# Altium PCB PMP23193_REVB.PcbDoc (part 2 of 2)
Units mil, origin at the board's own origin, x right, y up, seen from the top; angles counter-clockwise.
Board outline 5000 x 3500 mil, 4 copper layers (Component Side, Signal Layer 1, Signal Layer 2, Solder Side), stack 33.234 mil thick; 89 components, 40 nets, 217 pads, 130 vias.
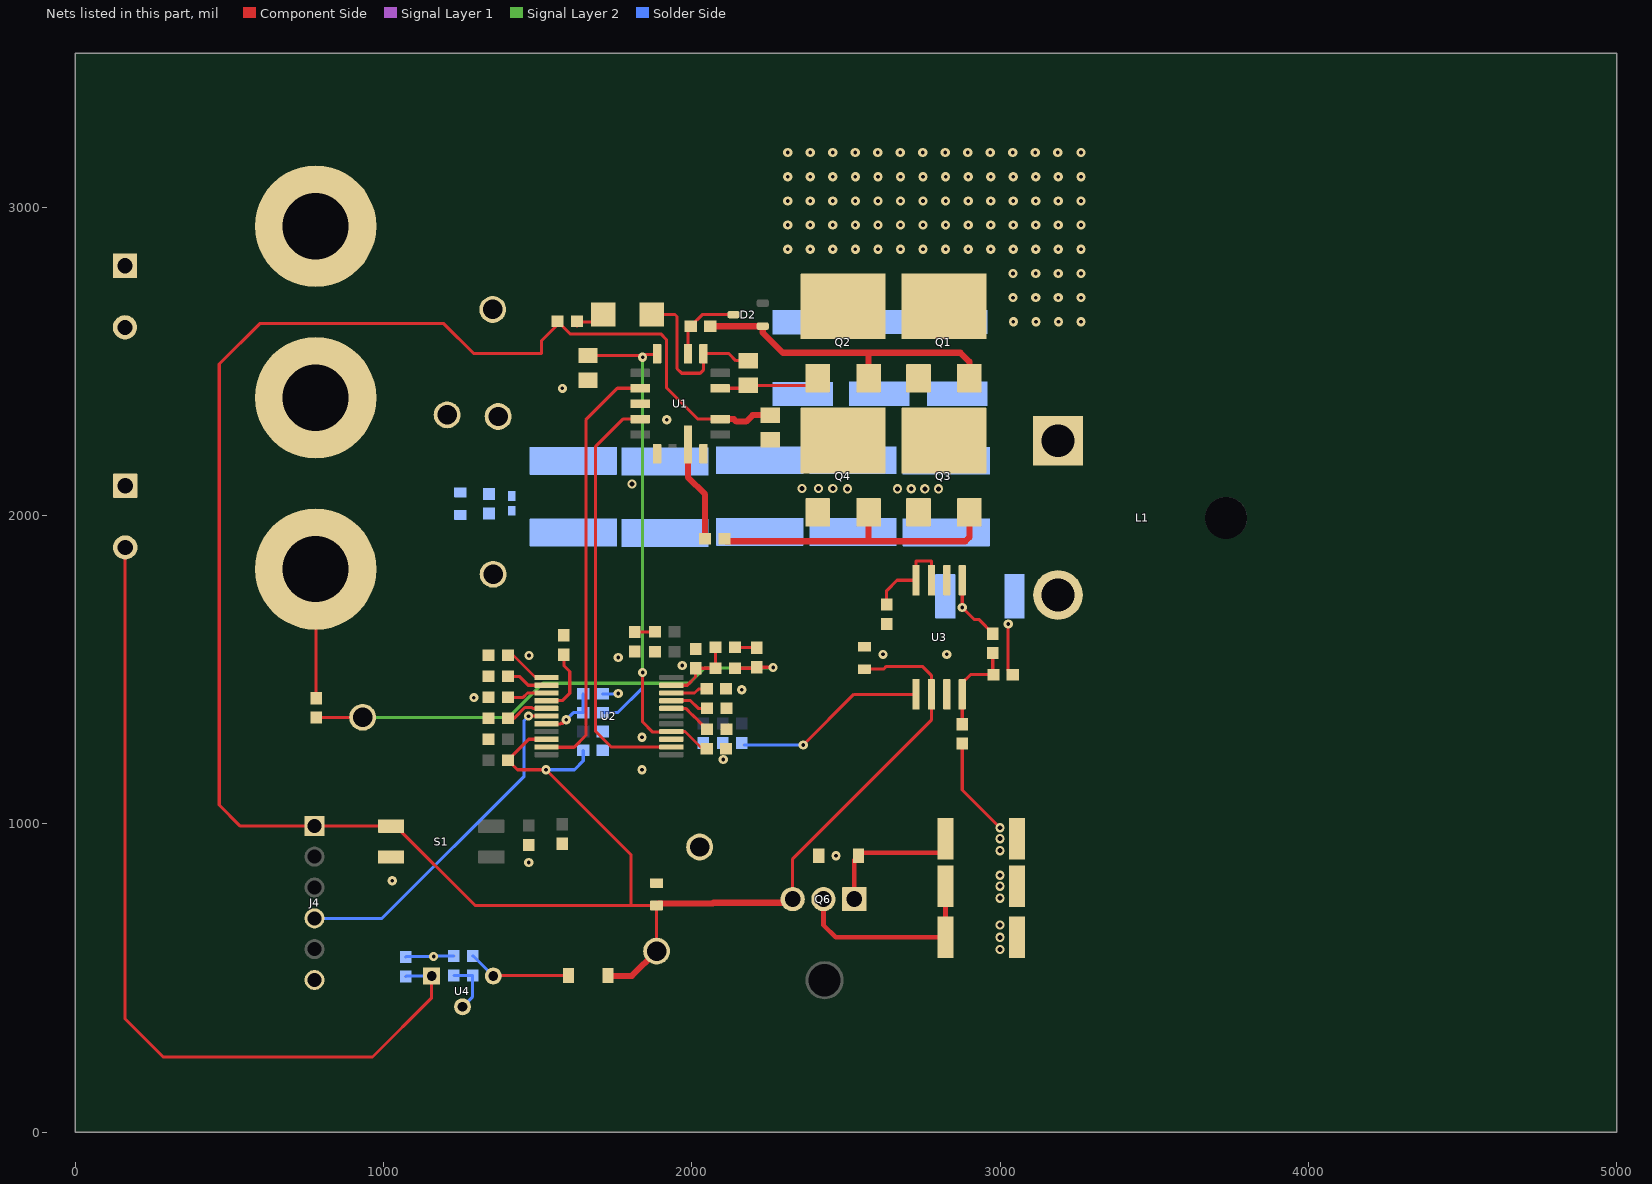
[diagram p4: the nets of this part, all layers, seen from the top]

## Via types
v1: diameter 30, hole 12, Component Side to Solder Side, tented both sides, 112 vias
v2: diameter 30, hole 16, Component Side to Solder Side, tented both sides, 18 vias

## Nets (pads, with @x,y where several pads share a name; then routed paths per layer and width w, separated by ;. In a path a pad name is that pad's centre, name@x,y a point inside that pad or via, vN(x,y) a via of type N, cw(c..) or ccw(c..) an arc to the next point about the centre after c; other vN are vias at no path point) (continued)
GND: C1.1 C2.2 C3.2 C11.2 C13.2 C15.1 C16.2 C17.2 C18.1 C19.1 C20.1 C21.1 C22.1 C23.2 C24.2 C26.2 C27.2 C28.2 C29.2 C30.1 C33.2 C35.1 C37.2 C38.2 C39.2 C200.2 D4.2 J1.2 J3.1 J4.6 J7.1 Q3.3 Q4.3 R6.1 R15.1 R16.1 R17.1 R18.1 R20.1 R21.1 R24.1 R25.1 R29.1 R31.1 R33.1 S1.4 TP2.1 TP4.1 TP7.1 U1.2 U1.14 U1.17 U2.14 U3.2 U3.7 | length 207.9
  Solder Side w10: C38.2@1072,568.5 1074,570.5 v1(1162.31,570.5) 1163.31,571.5 R33.1@1228,571.5 ; R24.1@1710.77,1422 1760,1422 v1(1761,1423)
  other v1: 1028,816 1471,875 2467.32,897 1838.57,1176 2101.89,1209 1838.57,1281.33 1293,1410 2162,1435.5 1968.93,1513.91 1761,1540 1471.93,1546.48 2619.91,1550.17 2827,1550.17 1918.5,2311.04 1580,2413
  other v2: 2504.97,2087.15 2667.1,2087.1 2755.6,2087.1 2799.96,2087.1 2357.63,2088.23 2410.81,2088.23 2457.31,2088.23 2711.71,2087.52 1805.5,2103.2
HIN: U1.13 U2.10 | length 1386.3
  Component Side w10: U2.10@1528.44,1249.04 1618.2,1249.04 1656,1286.84 1656,2311.04 1758.3,2413.34 U1.13@1832.56,2413.34
HOVgs: D2.1 Q1.2 Q2.2 R3.2 | length 1036.3
  Component Side w20: R3.2@2059.46,2615.29 2059.99,2614.75 D2.1@2230,2614.75 2230,2594.04 2295.51,2528.53 2573.18,2528.53 2573.33,2528.67 ; Q2.2@2573.33,2446.28 2573.33,2528.53 2871.1,2528.53 2900.1,2499.53 Q1.2@2900.1,2446.28
LIN: U1.15 U2.13 | length 1372.4
  Component Side w10: U1.15@1832.56,2313.34 1776.3,2313.34 1688,2225.04 1688,1300.03 1738.01,1250.02 U2.13@1933.56,1250.02
LOVgs: Q3.2 Q4.2 R4.2 | length 977.6
  Component Side w20: R4.2@2105.72,1924.67 2113.4,1916.98 2571.65,1916.98 2573.33,1918.66 ; Q4.2@2573.33,2010.88 2573.33,1918.66 ; Q3.2@2900.1,2010.88 2900.1,1929.69 2887.39,1916.98 2575,1916.98 2573.33,1918.66
NetC10_1: C10.1 D1.1 U1.8 | length 557.8
  Component Side w10: D1.1@1869.76,2652.71 1945.42,2652.71 1952,2646.12 1952,2477.04 1967,2462.04 2027,2462.04 2037.28,2472.32 U1.8@2037.28,2525.54 2120.24,2525.54 2142.76,2503.02 C10.1@2182.76,2503.02
NetC23_1: C23.1 U2.18 | length 145.2
  Component Side w10: U2.18@1933.56,1375.02 1980.03,1375.02 2002.18,1352.87 2003.36,1352.87 2019.68,1336.55 2019.68,1335.36 2020.67,1335.36 C23.1@2048.91,1307.12 C23.1@2047.93,1307.12
NetC24_1: C24.1 U2.5 | length 141
  Component Side w10: C24.1@1403.05,1343.04 1423.62,1343.04 1458.45,1377.87 1481.55,1377.87 1484.4,1375.02 U2.5@1528.44,1375.02
NetC25_2: C25.2 R29.2 | length 66.2
  Component Side w10: R29.2@1815,1622.53 1880.5,1622.53 C25.2@1881,1623.04
NetC28_1: C28.1 U2.20 | length 120.2
  Component Side w10: U2.20@1933.56,1425.02 2008.72,1425.02 2021.85,1438.15 C28.1@2048.27,1438.15
NetC34_1: C34.1 R23.1 | length 70.9
  Component Side w10: C34.1@2139.72,1573.03 2208.45,1573.03 R23.1@2209.99,1571.5
NetC37_1: C37.1 U3.3 U3.4 | length 329
  Component Side w10: C37.1@2632,1711.53 2632,1757.04 2665.69,1790.73 U3.4@2727,1790.73 2727,1853 2777,1853 U3.3@2777,1790.73
NetC201_1: C201.1 R200.2 R201.1 U3.8 | length 316.7
  Component Side w10: R201.1@2877,1323.55 U3.8@2877,1420.65 2877,1458.05 2903.6,1484.66 R200.2@2977.89,1484.66 2976.09,1486.46 C201.1@2976.09,1554.19
NetD1_2: D1.2 R1.2 | length 97.9
  Component Side w10: R1.2@1636.65,2629.04 D1.2@1688.61,2629.04
  Component Side w20: R1.2@1627.83,2620.23 R1.2@1636.65,2629.04 ; D1.2@1688.61,2629.04 D1.2@1712.28,2652.71
NetD2_3: D2.3 R3.1 U1.9 | length 247.9
  Component Side w10: U1.9@1987.28,2525.54 1987.28,2606.11 R3.1@1996.46,2615.29 2033.33,2652.15 D2.3@2135.51,2652.15
NetD4_1: D4.1 Q6.1 R10.1 | length 479.1
  Component Side w15: Q6.1@2526.93,744.57 2526.93,883.19 D4.1@2540.57,896.83 2550.41,906.68 2804.51,906.68 2822.6,924.77 R10.1@2822.6,952.36
NetD6_2: D6.2 R13.2 U4.3 | length 338.1
  Component Side w10: U4.3@1356,507.04 1357.96,509 D6.2@1599.53,509
  Solder Side w10: R13.2@1288.96,571.5 1291.54,571.5 U4.3@1356,507.04
NetL1_2: L1.2 R32.1 R200.1 | length 170.6
  Component Side w10: v1(3025.97,1648.54) 3025.97,1499.57 3026.2,1499.34 3026.2,1498.36 3039.9,1484.66 R200.1@3040.89,1484.66
NetQ6_2: Q6.2 R11.1 R12.1 | length 650.5
  Component Side w15: Q6.2@2426.93,744.57 2426.93,672.07 2466.54,632.46 R12.1@2822.6,632.46 R11.1@2822.6,798.41
NetR4_1: R4.1 U1.1 | length 329.4
  Component Side w20: U1.1@1987.28,2231.15 1987.28,2124.6 2042.72,2069.16 R4.1@2042.72,1924.67
NetR13_1: R13.1 R33.2 U4.2 | length 176.1
  Solder Side w10: R33.2@1228,508.5 R13.1@1288.96,508.5 1288.96,440 U4.2@1256,407.04
NetR14_2: R14.2 R23.2 R28.1 TP8.1 | length 1687.6
  Component Side w10: R28.1@781,1345.05 780.55,1345.5 TP8.1@931.87,1345.5 ; R14.2@2139.72,1505.22 2206.7,1505.22 R23.2@2209.99,1508.5 2262.63,1508.5 v1(2263.58,1507.55)
  Signal Layer 1 w10: TP8.1@932,1346 TP8.1@932,1367
  Signal Layer 2 w10: TP8.1@932,1346 1406,1346 1516.61,1456.61 1991.85,1456.61 2041.67,1506.44 v1@2254.61,1506.44
NetR15_2: R15.2 U2.3 | length 131.3
  Component Side w10: R15.2@1403.05,1410.88 1452.88,1410.88 1467.02,1425.02 U2.3@1528.44,1425.02
NetR16_2: R16.2 U2.2 | length 137.3
  Component Side w10: R16.2@1403.05,1478.78 1440.3,1478.78 1469.06,1450.02 U2.2@1528.44,1450.02
NetR17_2: R17.2 U2.1 | length 155.1
  Component Side w10: R17.2@1403.05,1546.69 1421.31,1546.69 1492.98,1475.02 U2.1@1528.44,1475.02
NetR19_1: R19.1 R24.2 U2.7 | length 203.4
  Component Side w10: U2.7@1528.44,1325.02 1573.6,1325.02 1575.45,1326.87 1581.37,1326.87 v1(1592.82,1338.32)
  Solder Side w10: v1@1587,1332.5 v1(1592.82,1338.32) 1615.54,1361.05 R19.1@1647.78,1361.05 R24.2@1647.78,1422
NetR20_2: R20.2 U2.4 | length 218.6
  Component Side w10: U2.4@1528.44,1400.02 1580.02,1400.02 1603.82,1423.82 1603.82,1494.73 1584.63,1513.91 R20.2@1584.63,1549.19
NetR25_2: R25.2 U2.19 | length 125.7
  Component Side w10: U2.19@1933.56,1400.02 1995.39,1400.02 2020.39,1375.02 R25.2@2048.91,1375.02
NetR30_2: R30.2 U3.5 | length 626.1
  Component Side w10: v1(2360.93,1256) 2525.58,1420.65 U3.5@2727,1420.65
  Solder Side w10: R30.2@2169.1,1256 v1(2360.93,1256)
SW: C10.2 L1.1 Q1.3 Q2.3 Q3.1 Q4.1 U1.6 | length 330
  Component Side w10: U1.6@2092.01,2413.34 C10.2@2173.07,2413.34 ; C10.2@2182.76,2423.02 2385.07,2423.02 Q2.3@2408.33,2446.28
  Component Side w20: C10.2@2173.07,2413.34 C10.2@2182.76,2423.02
SYNC: J4.4 U2.6 | length 1145.1
  Component Side w10: v1(1470,1350) U2.6@1528.44,1350.02
  Solder Side w10: J4.4@776,694 995,694 ; 1005.57,704.57 995,694 ; v1(1470,1350) 1456,1336 1456,1155 995,694
Vbias: C13.1 C30.2 C33.1 C35.2 D6.1 J4.1 Q6.3 R1.1 R8.2 S1.3 TP6.1 U1.4 U2.9 U3.6 | length 8117.7
  Component Side w10: U2.9@1528.44,1275.02 1470.9,1275.02 R8.2@1403.05,1207.16 1434.21,1176 v1(1527,1176) 1802,901 1802,735.42 ; R1.1@1564.57,2630.04 1604.61,2590 1899,2590 1918,2571 1918,2415 2019.66,2313.34 U1.4@2092.01,2313.34 ; R1.1@1564.84,2620.23 1512.83,2568.22 1512.83,2526.03 1292.3,2526.03 1195.33,2623 598,2623 467,2492 467,1061.42 535.38,993.04 S1.3@1024.6,993.04 1039.62,993.04 1297.25,735.42 1802,735.42 ; TP6.1@1885.59,587.78 C30.2@1885.59,735.42 1802,735.42 ; Q6.3@2326.93,744.57 2326.93,886.93 2777,1337 U3.6@2777,1420.65 2777,1482 2747.46,1511.54 2631,1511.54 2621.74,1502.28 C35.2@2560,1502.28
  Component Side w20: D6.1@1728.47,509 1730.43,507.04 1804.85,507.04 TP6.1@1885.59,587.78 ; C30.2@1885.59,735.42 1892.09,741.91 2067.68,741.91 2070.33,744.57 Q6.3@2326.93,744.57 ; U1.4@2092.01,2313.34 2136.21,2313.34 2144.28,2305.27 2175.87,2305.27 2196.81,2326.21 C13.1@2254.61,2326.21
  Solder Side w10: v1(1527,1176) 1619.06,1176 1647.78,1204.72 C33.1@1647.78,1239.01
Vfb: C34.2 R14.1 R21.2 U2.21 | length 250.5
  Component Side w10: U2.21@1933.56,1450.02 1985.26,1450.02 2011.93,1476.7 R21.2@2011.93,1505.22 R14.1@2076.72,1505.22 C34.2@2076.72,1573.03
Vin: C1.2 C2.1 C3.1 J1.1 J2.1 Q1.1 Q2.1 R10.2 R11.2 R12.2 R201.2 TP1.1 | length 323.4
  Component Side w10: R201.2@2877,1260.56 2877,1110.44 v2(2999.54,987.9)
  other v1: 3043,2629 3116,2629 3189,2629 3262,2629 3041.67,2707.43 3115.11,2707.43 3188.56,2707.43 3262,2707.43 3041.67,2785.86 3115.11,2785.86 3188.56,2785.86 3262,2785.86 2311,2864.29 2384.15,2864.29 2457.31,2864.29 2530.46,2864.29 2603.62,2864.29 2676.77,2864.29 2749.92,2864.29 2823.08,2864.29 2896.23,2864.29 2969.38,2864.29 3042.54,2864.29 3115.69,2864.29 3188.85,2864.29 3262,2864.29 2311,2942.71 2384.15,2942.71 2457.31,2942.71 2530.46,2942.71 2603.62,2942.71 2676.77,2942.71 2749.92,2942.71 2823.08,2942.71 2896.23,2942.71 2969.38,2942.71 3042.54,2942.71 3115.69,2942.71 3188.85,2942.71 3262,2942.71 2311,3021.14 2384.15,3021.14 2457.31,3021.14 2530.46,3021.14 2603.62,3021.14 2676.77,3021.14 2749.92,3021.14 2823.08,3021.14 2896.23,3021.14 2969.38,3021.14 3042.54,3021.14 3115.69,3021.14 3188.85,3021.14 3262,3021.14 2311,3099.57 2384.15,3099.57 2457.31,3099.57 2530.46,3099.57 2603.62,3099.57 2676.77,3099.57 2749.92,3099.57 2823.08,3099.57 2896.23,3099.57 2969.38,3099.57 3042.54,3099.57 3115.69,3099.57 3188.85,3099.57 3262,3099.57 2311,3178 2384,3178 2457,3178 2530,3178 2603,3178 2676,3178 2749,3178 2822,3178 2895,3178 2968,3178 3041,3178 3114,3178 3187,3178 3262,3178
  other v2: 2999.54,592.99 2999.29,632.46 2999.29,672.07 2999.29,759.4 2999.54,798.39 2999.54,833.69 2999.54,913.58 2999.54,952.36
VLDO: C11.1 C27.1 R19.2 U1.11 U2.15 | length 1877.8
  Component Side w10: C11.1@1663.17,2519.56 1838.39,2519.56 1841.7,2522.87 1883.64,2522.87 U1.11@1886.8,2526.03 ; v1(1840.25,1491.37) 1840.25,1330.75 1873,1298 1931.54,1298 U2.15@1933.56,1300.02 1977.96,1300.02 2034.46,1243.52 C27.1@2048.27,1243.52
  Component Side w20: U1.11@1886.8,2526.03 U1.11@1887.28,2525.54
  Signal Layer 1 w10: v1@1840.25,2521.42 v1@1841.7,2522.87
  Signal Layer 2 w10: v1(1840.25,1491.37) v1@1840.25,2521.42
  Solder Side w10: R19.2@1710.77,1361.05 1759.02,1361.05 1840.25,1442.27 v1(1840.25,1491.37)
  other v1: 1840.25,2513.89
Vout: C15.2 C16.1 C17.1 C18.2 C19.2 C20.2 C21.2 C22.2 C38.1 C201.2 J3.2 J6.1 R28.2 R32.2 TP3.1 U3.1 U4.1 | length 3440.4
  Component Side w10: J3.2@161.1,1884.2 161.1,367.9 285,244 964,244 1156,436 U4.1@1156,507.04 ; J6.1@779.7,1826.72 781,1825.42 R28.2@781,1408.04 ; U3.1@2877,1790.73 v1(2877,1702.04) 2915.35,1663.69 2930.57,1663.69 2976.09,1618.17 C201.2@2976.09,1617.19
  Solder Side w10: C38.1@1072,505.5 1073.53,507.04 U4.1@1156,507.04
pads on no net: D2.2 H1.1 J4.2 J4.3 J4.5 L1. U1.3 U1.7 U1.12 U1.16 U1.18 U2.11 U2.12

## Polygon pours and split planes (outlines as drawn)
GND on Solder Side "Solder Side-SGND" (solid, pour order 24): 0,0 5000,0 5000,3500 0,3500
Vout on Solder Side "Solder Side-Vout" (solid, pour order 6): 2985.09,2031 2985.09,1585.69 0,1585.69 0,2031
NetL1_2 on Solder Side "Solder Side-IN+" (solid, pour order 15): 3005,1586 3005,1900.94 3029.09,1925.04 3311,1925.04 3311,1586
Vin on Solder Side "Solder Side-Vin" (solid, pour order 2): 5000,2564.9 5000,3500 0,3500 0,2756 570.4,2756 623.7,2702.7 1038.3,2702.7 1176.1,2564.9
Vin on Component Side "Component Side-Vin" (solid, pour order 0): 3106,539.07 3106,1044 2958.42,1044 2958.43,539.07
GND on Component Side "Component Side-SGND" (solid, remove dead copper, pour order 25): 0,0 0,3500 5000,3500 5000,0
SW on Component Side "Component Side-SW" (solid, pour order 16): 2352,2350.21 2352,2493.04 2448.13,2493.04 2448.13,2400 2497.92,2350.21 2678,2350.21 2678,2493.04 2775,2493.04 2775,2400.13 2824.92,2350.21 3271.34,2350.21 3271.34,2137.58 2954.86,2137.58 2352,2138.52
Vin on Component Side "Component Side-Vin" (solid, pour order 10): 3305,2564.9 3305,3225 2270,3225 2270,2564.9
Vin on Signal Layer 2 "Signal Layer 2-GND" (solid, pour order 18): 0,0 5000,0 5000,3500 0,3500
GND on Signal Layer 1 "Signal Layer 2-GND" (solid, pour order 22): 0,0 5000,0 5000,3500 0,3500

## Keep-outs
Keep-Out Layer:
  text ".Layer_Name" at 577,-858.49 h60

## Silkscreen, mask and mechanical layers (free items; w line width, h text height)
Top Overlay:
  text "VIN" at 84,2996 h100
  text "VOUT" at 84,1586 h100
  text "Vbias" at 409,972 h60
  text "SYNC" at 457.63,658.16 h60
  text "SGND" at 447.91,465 h60
  text "'.PRJ_Number'.PCB_Rev" at 4113.85,124 h108.27
  text ".Layer_Name" at 577,-858.49 h60
Bottom Overlay:
  text ".Layer_Name" at 577,-858.49 h60
Top Paste:
  text ".Layer_Name" at 577,-858.49 h60
Bottom Paste:
  text ".Layer_Name" at 577,-858.49 h60
Top Solder:
  text ".Layer_Name" at 577,-858.49 h60
  text ".Layer_Name" at 577,-858.49 h60
Bottom Solder:
  text ".Layer_Name" at 577,-858.49 h60
Drill Guide:
  text ".Layer_Name" at 577,-858.49 h60
M1 Board Outline:
  lines w10: 0,4000 0,4005 ; 0,0 0,3500 5000,3500 5000,0 0,0
  text ".Layer_Name" at 577,-858.49 h60
M2 Board Dimensions:
  rectangle: 0,-275 125,-150
  rectangle: 125,-400 500,-275
  lines w7: 0,-275 1000,-275 ; 125,-400 125,-150 ; 250,-400 250,-150 ; 500,-400 500,-150 ; 750,-400 750,-150 ; 0,-400 1000,-400 1000,-150 0,-150 0,-400
  text ".Layer_Name" at 577,-858.49 h60
M3 3D STEP Top:
  text ".Layer_Name" at 577,-858.49 h60
M4 3D STEP Bottom:
  text ".Layer_Name" at 577,-858.49 h60
M5 Assembly Top:
  lines w10: -292,-930.17 6308,-930.17 ; -292,-726.83 6310,-726.83 ; -292,-523.5 -292,-1133.5 3713,-1133.5 6310,-1133.5 6310,-523.5 -291.5,-523.5 -291.5,-1133.5 1284,-1133.5 ; 2173,-1133.5 2173,-523.5 ; 3440,-726.83 3440,-523.5 ; 4280,-726.83 4280,-523.5 ; 4902,-1140 4902,-937.17
  text "COMPONENTS MARKED 'DNP' SHOULD NOT BE POPULATED." at 1153.5,-318.5 h60
  text "ASSEMBLY VARIANT:" at 1153,-434 h60
  text ".VariantName" at 2189,-434 h60
  text "PCB VIEWED FROM TOP SIDE" at -228.5,-655.67 h60
  text "BOARD #:" at 2248,-655.67 h60
  text ".PRJ_Number" at 2793.5,-655.67 h60
  text "REV:" at 3638,-655.67 h60
  text ".PCB_Rev" at 3929.5,-655.67 h60
  text "SVN REV:" at 4476,-655.67 h60
  text ".VersionControl_RevNumber" at 4982,-655.67 h60
  text "TID #:" at 2248,-859 h60
  text ".TID" at 2793.5,-859 h60
  text "PLOT NAME =" at -228.5,-1064.34 h60
  text ".plot_File_Name" at 577,-1064.34 h60
  text "GENERATED    :" at 2250,-1064.34 h60
  text ".Print_Date" at 3119.5,-1064.34 h60
  text ".Print_Time" at 3848.5,-1064.34 h60
  text "TEXAS INSTRUMENTS" at 5113,-1064.34 h60
M6 Assembly Bottom:
  lines w10: -292.5,-727.33 6309.5,-727.33 ; -290.5,-930.67 6309.5,-930.67 ; 1115.5,-1140.5 1115.5,-937.67 ; 1737.5,-727.33 1737.5,-524 ; 2577.5,-727.33 2577.5,-524 ; 3844.5,-1134 3844.5,-524 ; 4733.5,-1134 6309,-1134 6309,-524 -292.5,-524 -292.5,-1134 2304.5,-1134 6309.5,-1134 6309.5,-524
  text "COMPONENTS MARKED 'DNP' SHOULD NOT BE POPULATED." at 6102,-318 h60
  text ".VariantName" at 5058,-434 h60
  text "ASSEMBLY VARIANT:" at 6097,-434 h60
  text ".VersionControl_RevNumber" at 1035.5,-656.17 h60
  text "SVN REV:" at 1541.5,-656.17 h60
  text ".PCB_Rev" at 2088,-656.17 h60
  text "REV:" at 2379.5,-656.17 h60
  text ".PRJ_Number" at 3224,-656.17 h60
  text "BOARD #:" at 3769.5,-656.17 h60
  text "PCB VIEWED FROM BOTTOM SIDE" at 6246,-656.17 h60
  text ".TID" at 3224,-859.5 h60
  text "TID #:" at 3769.5,-859.5 h60
  text "TEXAS INSTRUMENTS" at 904.5,-1064.84 h60
  text ".Print_Time" at 2169,-1064.84 h60
  text ".Print_Date" at 2898,-1064.84 h60
  text "GENERATED    :" at 3767.5,-1064.84 h60
  text ".plot_File_Name" at 5440.5,-1064.84 h60
  text "PLOT NAME =" at 6246,-1064.84 h60
M9 Title Sheet:
  drawing of 57 lines, arcs and shapes, not listed
  text "1" at 739.84,8036.5 h70
  text "2" at 3235.5,8036.5 h70
  text "3" at 5724.84,8036.5 h70
  text "4" at 8231.51,8036.5 h70
  text "5" at 10730.5,8036.5 h70
  text "6" at 13235.5,8036.5 h70
  text "A" at -416.5,6893.5 h70
  text "A" at 14383.5,6893.5 h70
  text "B" at -416.5,4513.5 h70
  text "B" at 14383.5,4513.5 h70
  text "C" at -416.5,2138.5 h70
  text "C" at 14383.5,2138.5 h70
  text "PROJECT TITLE:" at 11343.5,277.5 h45
  text ".PRJ_Title" at 11393.5,144.17 h70
  text "DESIGNED FOR:" at 11343.5,-23.5 h45
  text ".PRJ_Customer" at 11393.5,-163.5 h70
  text "D" at -416.5,-231.5 h70
  text "D" at 14383.5,-231.5 h70
  text "FILE NAME:" at 11343.5,-323.5 h45
  text ".PCB_File_Name_No_Path" at 11393.5,-443.5 h70
  text "Texas Instruments (TI) and/or its licensors do not warrant the accuracy or completeness of this specification" at 6374,-605.34 h45
  text "ENGINEER:" at 11343.5,-613.5 h45
  text "LAYOUT BY:" at 12848.5,-613.5 h45
  text "or any information contained therein. TI and/or its licensors do not warrant that this design will meet" at 6329.01,-718 h45
  text ".PRJ_Engineer" at 11393.5,-768.49 h70
  text ".PCB_Layout" at 12899,-768.49 h70
  text "the specifications, will be suitable for your application or fit for any particular purpose, or will operate in" at 6329.01,-830.67 h45
  text ".Layer_Name" at 577,-858.49 h60
  text "ALTIUM DESIGNER VERSION:" at 12848.5,-923.5 h45
  text "an implementation. TI and/or its licensors do not warrant that the design is production worthy. You should" at 6329.01,-943.33 h45
  text "completely validate and test your design implementation to confirm the system functionality for your application." at 6374,-1056 h45
  text ".print_Scale" at 11393.5,-1056.83 h70
  text ".Application_BuildNumber" at 12899,-1056.83 h70
  text "1" at 739.84,-1263.5 h70
  text "2" at 3235.5,-1263.5 h70
  text "3" at 5724.84,-1263.5 h70
  text "4" at 8231.51,-1263.5 h70
  text "5" at 10730.5,-1263.5 h70
  text "6" at 13235.5,-1263.5 h70
M10 Fab Notes:
  drawing of 189 lines, arcs and shapes, not listed
  text "DESIGN INFORMATION" at 12382.02,6356.17 h60
  text "MIN. TRACK WIDTH:" at 11737.46,6224.05 h60
  text "8" at 12833.7,6224.05 h60
  text "MIL" at 12988.46,6224.05 h60
  text "7.874" at 12667.32,6102.36 h60
  text "MIN. CLEARANCE:" at 11737.46,6099.92 h60
  text "MIL" at 12988.46,6099.92 h60
  text "MIN. VIA PAD SIZE:" at 11737.46,5975.8 h60
  text "24" at 12803.71,5975.8 h60
  text "MIL" at 12988.46,5975.8 h60
  text "0.05mm (2MIL)" at 12432.46,5845.9 h60
  text "MINIMUM ANNULAR RING" at 11408.23,5837.67 h60
  text "EXTERNAL" at 13140.46,5837.67 h60
  text "PER" at 11608.23,5727.55 h60
  text "IPC-D-275 CLASS 2 LEVEL C" at 11828.23,5727.54 h60
  text "MIL, HOLES" at 13316.46,5627.07 h60
  text "+/-" at 12924,5618.48 h60
  text "+/-" at 13778,5618.48 h60
  text "REGISTRATION TOLERANCES:" at 11408.23,5617.42 h60
  text "METAL" at 12608,5617.42 h60
  text "5" at 13184.2,5617.42 h60
  text "3" at 14017.2,5617.42 h60
  text "MIL" at 14133.46,5617.42 h60
  text "HOLE SIZE TOLERANCE (UNLESS OTHERWISE SPECIFIED):" at 11408.23,5519.1 h60
  text "+/-" at 13778,5516.23 h60
  text "3" at 14017.2,5515.17 h60
  text "MIL" at 14133.46,5515.17 h60
  text "MATERIAL:" at 11333.46,5377.52 h60
  text "FR-4 High Tg" at 12319.9,5249 h60
  text "X" at 12175.46,5241.01 h60
  text "FR-408" at 11754.46,5236.49 h60
  text "OTHER" at 13242.46,5236.49 h60
  text "62 MIL (1.6mm) +/-10%" at 12074.56,5093.46 h60
  text "X" at 11954.46,5091.01 h60
  text "THICKNESS:" at 11408.23,5085.24 h60
  text "OTHER" at 13359.46,5085.24 h60
  text "TOLERANCE:" at 11408.23,4946.92 h60
  text "X" at 12256.46,4946.92 h60
  text "ANSI IPC-6012 TYPE 3 CLASS 2" at 12434.48,4946.92 h60
  text "OTHER +/-" at 12434.46,4802.73 h60
  text "BOW & TWIST:" at 11408.23,4657.54 h60
  text "X" at 12256.46,4657.54 h60
  text "ANSI IPC-6012 TYPE 3 CLASS 2" at 12434.48,4657.54 h60
  text "OTHER +/-" at 12434.46,4510.85 h60
  text "DRILLING:" at 11333.46,4380.23 h60
  text "NC_DRILL FILES" at 13094.46,4275.04 h60
  text "REFERENCE:" at 11408.23,4271.1 h60
  text "X" at 12065.46,4271.01 h60
  text "AS SHOWN" at 12243.46,4271.1 h60
  text "X" at 12966.46,4271.1 h60
  text "OTHER" at 13392.46,4128.85 h60
  text "PTH COPPER THICKNESS:" at 11407.91,4125.32 h60
  text "X" at 12547.14,4125.32 h60
  text "20-30 um" at 12675.14,4125.32 h60
  text "BOARD FINISH:" at 11333.46,3977.73 h60
  text "SILKSCREEN:" at 11488.68,3867.6 h60
  text "X" at 12446.46,3867.6 h60
  text "TOP" at 12563.46,3867.6 h60
  text "X" at 12956.46,3867.6 h60
  text "BOTTOM" at 13074.46,3867.6 h60
  text "SILKSCREEN COLOR:" at 11488.68,3712.41 h60
  text "X" at 12445.46,3712.41 h60
  text "WHITE" at 12563.46,3712.41 h60
  text "OTHER" at 13074.46,3712.41 h60
  text "X" at 12576.46,3568.96 h60
  text "GREEN" at 12694.46,3568.96 h60
  text "OTHER" at 13312.46,3568.96 h60
  text "SOLDER RESIST COLOR:" at 11488.68,3562.1 h60
  text "X" at 12576.46,3414.71 h60
  text "MATTE" at 12694.46,3414.71 h60
  text "SEMI-GLOSS" at 13312,3414.07 h60
  text "IMMERSION GOLD (ENIG)" at 12394.46,3241.94 h60
  text "ENEPIG" at 13732,3234.72 h60
  text "SURFACE FINISH:" at 11333.46,3233.72 h60
  text "X" at 12216.46,3233.72 h60
  text "IMM. TIN/SILVER OR EQUIV" at 11663,3096.4 h60
  text "OTHER" at 13094.46,3092.47 h60
  text "ARRAY/PANEL:" at 11333.46,2937.09 h60
  text "CUT AND TRIM PER M1 BOARD OUTLINE" at 12394.46,2928.87 h60
  text "N.C. ROUTE" at 12394.46,2792.9 h60
  text "X" at 13082.46,2792.9 h60
  text "V. SCORE" at 13260.46,2792.9 h60
  text "CERTIFICATION:" at 11333.46,2663.77 h60
  text "MATERIALS AND WORKMANSHIP FOR ALL PCBS" at 12058.46,2663.77 h60
  text "TO MEET OR EXCEED THE REQUIREMENTS OF:" at 12058.46,2569.71 h60
  text "X" at 11695.97,2441.08 h60
  text "ANSI IPC-A-600F CLASS ->" at 11823.96,2441.08 h60
  text "X" at 13471.97,2441.08 h60
  text "2" at 13581.96,2441.08 h60
  text "1" at 13266.96,2439.58 h60
  text "3" at 13935.96,2439.58 h60
  text "X" at 12507.97,2293.39 h60
  text "RoHS" at 12635.96,2293.39 h60
  text "OTHER" at 13280.36,2293.39 h60
  text "PER ORDER" at 13677.42,2293.39 h60
  text "ALL BOARDS MUST MEET OR EXCEED UL94-V0 REQUIREMENTS." at 11361,2139.57 h60
  text "PCB MUST BEAR THE UL94V-0 UL REGISTERED MATERIAL ID NUMBER" at 11361,2023.5 h60
  text "ADDITIONAL REQUIREMENTS:" at 11333.46,1854.08 h60
  text "MICROSECTION:" at 11408.23,1746.95 h60
  text "YES" at 12313.96,1746.95 h60
  text "REQUIRED" at 13175.46,1602.62 h60
  text "BARE BOARD ELEC. TEST:" at 11408.23,1599.76 h60
  text "NONE" at 12713.96,1599.76 h60
  text "X" at 13057.46,1599.76 h60
  text "PER ORDER" at 13767.46,1599.76 h60
  text "XX MIL VIAS REQUIRE NON-CONDUCTIVE FILL AND PLANARIZE" at 11576.38,1394.82 h59
  text "XX MIL VIAS REQUIRE CONDUCTIVE FILL AND PLANARIZE" at 11584.38,1290.84 h60
  text "OUTER XX MIL TRACES REQUIRE 50 OHM SINGLE-ENDED IMPEDANCE" at 11583.39,1127.46 h58
  text "LAYER 2 & 3 (INNER LAYERS) XX MIL WIDE, XX MIL SPACE / TRACES REQUIRE 100 OHM DIFFERENTIAL IMPEDANCE" at 11575.39,891.74 h60
  text ".Layer_Name" at 577,-858.49 h60
M11 Gerber Information:
  lines w10: -292,-930.17 6308,-930.17 ; -292,-726.83 6310,-726.83 ; -292,-523.5 -292,-1133.5 3713,-1133.5 6310,-1133.5 6310,-523.5 -291.5,-523.5 -291.5,-1133.5 1284,-1133.5 ; 2173,-1133.5 2173,-523.5 ; 3440,-726.83 3440,-523.5 ; 4280,-726.83 4280,-523.5 ; 4902,-1140 4902,-937.17
  text "ALL ARTWORK VIEWED FROM TOP SIDE" at -228.5,-655.67 h60
  text "BOARD #:" at 2248,-655.67 h60
  text ".PRJ_Number" at 2793.5,-655.67 h60
  text "REV:" at 3638,-655.67 h60
  text ".PCB_Rev" at 3929.5,-655.67 h60
  text "SVN REV:" at 4476,-655.67 h60
  text ".VersionControl_RevNumber" at 4982,-655.67 h60
  text "LAYER NAME =" at -228.5,-858.49 h60
  text "TID #:" at 2248,-859 h60
  text ".TID" at 2793.5,-859 h60
  text "PLOT NAME =" at -228.5,-1064.34 h60
  text ".plot_File_Name" at 577,-1064.34 h60
  text "GENERATED    :" at 2250,-1064.34 h60
  text ".Print_Date" at 3119.5,-1064.34 h60
  text ".Print_Time" at 3848.5,-1064.34 h60
  text "TEXAS INSTRUMENTS" at 5113,-1064.34 h60
M12 Stackup:
  drawing of 295 lines, arcs and shapes, not listed
  text "Layer" at 9821.59,7649.94 h60
  text "Name" at 10231.51,7649.94 h60
  text "Material" at 11171.25,7649.94 h60
  text "Thickness" at 12031.02,7649.94 h60
  text "Constant" at 12680.85,7649.94 h60
  text "Board Layer Stack" at 13250.71,7649.94 h60
  text "Top Overlay" at 10231.51,7529.94 h60
  text "Top Solder" at 10231.51,7409.94 h60
  text "Solder Resist" at 11171.25,7409.94 h60
  text "0.40mil" at 12031.02,7409.94 h60
  text "3.5" at 12680.85,7409.94 h60
  text "1" at 9821.59,7289.94 h60
  text "Component Side" at 10231.51,7289.94 h60
  text "1.40mil" at 12031.02,7289.94 h60
  text "Dielectric 1" at 10231.51,7169.94 h60
  text "FR-4" at 11171.25,7169.94 h60
  text "12.60mil" at 12031.02,7169.94 h60
  text "4.8" at 12680.85,7169.94 h60
  text "2" at 9821.59,7049.94 h60
  text "Signal Layer 1" at 10231.51,7049.94 h60
  text "1.42mil" at 12031.02,7049.94 h60
  text "Dielectric 3" at 10231.51,6929.94 h60
  text "5.00mil" at 12031.02,6929.94 h60
  text "4.2" at 12680.85,6929.94 h60
  text "3" at 9821.59,6809.94 h60
  text "Signal Layer 2" at 10231.51,6809.94 h60
  text "1.42mil" at 12031.02,6809.94 h60
  text "Dielectric 4" at 10231.51,6689.94 h60
  text "10.00mil" at 12031.02,6689.94 h60
  text "4.2" at 12680.85,6689.94 h60
  text "4" at 9821.59,6569.94 h60
  text "Solder Side" at 10231.51,6569.94 h60
  text "1.40mil" at 12031.02,6569.94 h60
  text "Bottom Solder" at 10231.51,6449.94 h60
  text "Solder Resist" at 11171.25,6449.94 h60
  text "0.40mil" at 12031.02,6449.94 h60
  text "3.5" at 12680.85,6449.94 h60
  text "Bottom Overlay" at 10231.51,6329.94 h60
  text ".Layer_Name" at 577,-858.49 h60
M13 Component Bodies Top:
  text ".Layer_Name" at 577,-858.49 h60
M14 Component Bodies Bottom:
  text ".Layer_Name" at 577,-858.49 h60
M15 Courtyards Top:
  text ".Layer_Name" at 577,-858.49 h60
M16 Courtyards Bottom:
  text ".Layer_Name" at 577,-858.49 h60
Drill Drawing:
  circle w10: c8124.43,2846.34 r27.63
  lines w10: 8096.81,2252.37 8152.06,2252.37 8124.43,2197.12 8096.81,2252.37 ; 8096.81,2335.25 8110.62,2335.25 8110.62,2321.44 8138.25,2321.44 8138.25,2335.25 8152.06,2335.25 8152.06,2362.88 8138.25,2362.88 8138.25,2376.69 8110.62,2376.69 8110.62,2362.88 8096.81,2362.88 8096.81,2335.25 ; 8096.81,2445.76 8096.81,2459.57 8110.62,2473.38 8096.81,2487.2 8096.81,2501.01 8110.62,2501.01 8124.43,2487.2 8138.25,2501.01 8152.06,2501.01 8152.06,2487.2 8138.25,2473.38 8152.06,2459.57 8152.06,2445.76 8138.25,2445.76 8124.43,2459.57 8110.62,2445.76 8096.81,2445.76 ; 8096.81,2570.08 8152.06,2570.08 8152.06,2625.33 8096.81,2625.33 8096.81,2570.08 ; 8096.81,2694.4 8152.06,2694.4 8152.06,2749.65 8096.81,2749.65 8096.81,2694.4 ; 8096.81,2956.85 8110.62,2956.85 8124.43,2943.04 8138.25,2956.85 8152.06,2956.85 8138.25,2970.66 8152.06,2984.48 8138.25,2984.48 8124.43,2998.29 8110.62,2984.48 8096.81,2984.48 8110.62,2970.66 8096.81,2956.85 ; 8096.81,3081.17 8110.62,3081.17 8124.43,3067.36 8138.25,3081.17 8152.06,3081.17 8138.25,3094.98 8152.06,3108.8 8138.25,3108.8 8124.43,3122.61 8110.62,3108.8 8096.81,3108.8 8110.62,3094.98 8096.81,3081.17 ; 8096.81,3246.93 8152.06,3246.93 8124.43,3191.68 8096.81,3246.93 ; 8096.81,3343.62 8124.43,3316 8152.06,3343.62 8124.43,3371.25 8096.81,3343.62 ; 8096.81,3440.32 8124.43,3454.13 8152.06,3440.32 8138.25,3467.94 8152.06,3495.57 8124.43,3481.76 8096.81,3495.57 8110.62,3467.94 8096.81,3440.32 ; 8107.86,2705.45 8141.01,2705.45 8141.01,2738.6 8107.86,2738.6 8107.86,2705.45 ; 8107.86,3086.7 8116.14,3086.7 8124.43,3078.41 8132.72,3086.7 8141.01,3086.7 8132.72,3094.98 8141.01,3103.27 8132.72,3103.27 8124.43,3111.56 8116.14,3103.27 8107.86,3103.27 8116.14,3094.98 8107.86,3086.7 ; 8107.86,3235.88 8141.01,3235.88 8124.43,3202.73 8107.86,3235.88
  lines w12: 8046.72,2159.82 11393.37,2159.82 ; 8046.72,3527.34 11393.37,3527.34 ; 8384.58,2035.5 8384.58,3651.66 ; 8716.58,2035.5 8716.58,3651.66 ; 9353.14,2035.5 9353.14,3651.66 ; 9612.28,2035.5 9612.28,3651.66 ; 9987.44,2035.5 9987.44,3651.66 ; 10826.93,2035.5 10826.93,3651.66 ; 8046.72,2035.5 11393.37,2035.5 11393.37,3651.66 8046.72,3651.66 8046.72,2035.5
  text "Symbol" at 8121.31,3564.64 h72
  text "Quantity" at 8421.87,3564.64 h72
  text "Finished Hole Size" at 8753.87,3564.64 h72
  text "Plated" at 9390.44,3564.64 h72
  text "Hole Type" at 9649.58,3564.64 h72
  text "Drill Layer Pair" at 10024.74,3564.64 h72
  text "Hole Tolerance" at 10864.23,3564.64 h72
  text "1" at 8421.87,3440.32 h60
  text "136.00mil (3.454mm)" at 8753.87,3440.32 h60
  text "NPTH" at 9390.44,3440.32 h60
  text "Round" at 9649.58,3440.32 h60
  text "Component Side - Solder Side" at 10024.74,3440.32 h60
  text "112" at 8421.87,3316 h60
  text "12.00mil (0.305mm)" at 8753.87,3316 h60
  text "PTH" at 9390.44,3316 h60
  text "Round" at 9649.58,3316 h60
  text "Component Side - Solder Side" at 10024.74,3316 h60
  text "18" at 8421.87,3191.68 h60
  text "16.00mil (0.406mm)" at 8753.87,3191.68 h60
  text "PTH" at 9390.44,3191.68 h60
  text "Round" at 9649.58,3191.68 h60
  text "Component Side - Solder Side" at 10024.74,3191.68 h60
  text "3" at 8421.87,3067.36 h60
  text "31.50mil (0.800mm)" at 8753.87,3067.36 h60
  text "PTH" at 9390.44,3067.36 h60
  text "Round" at 9649.58,3067.36 h60
  text "Component Side - Solder Side" at 10024.74,3067.36 h60
  text "6" at 8421.87,2943.04 h60
  text "45.28mil (1.150mm)" at 8753.87,2943.04 h60
  text "PTH" at 9390.44,2943.04 h60
  text "Round" at 9649.58,2943.04 h60
  text "Component Side - Solder Side" at 10024.74,2943.04 h60
  text "4" at 8421.87,2818.72 h60
  text "49.21mil (1.250mm)" at 8753.87,2818.72 h60
  text "PTH" at 9390.44,2818.72 h60
  text "Round" at 9649.58,2818.72 h60
  text "Component Side - Solder Side" at 10024.74,2818.72 h60
  text "3" at 8421.87,2694.4 h60
  text "51.18mil (1.300mm)" at 8753.87,2694.4 h60
  text "PTH" at 9390.44,2694.4 h60
  text "Round" at 9649.58,2694.4 h60
  text "Component Side - Solder Side" at 10024.74,2694.4 h60
  text "7" at 8421.87,2570.08 h60
  text "63.00mil (1.600mm)" at 8753.87,2570.08 h60
  text "PTH" at 9390.44,2570.08 h60
  text "Round" at 9649.58,2570.08 h60
  text "Component Side - Solder Side" at 10024.74,2570.08 h60
  text "1" at 8421.87,2445.76 h60
  text "104.33mil (2.650mm)" at 8753.87,2445.76 h60
  text "PTH" at 9390.44,2445.76 h60
  text "Round" at 9649.58,2445.76 h60
  text "Component Side - Solder Side" at 10024.74,2445.76 h60
  text "2" at 8421.87,2321.44 h60
  text "106.30mil (2.700mm)" at 8753.87,2321.44 h60
  text "PTH" at 9390.44,2321.44 h60
  text "Round" at 9649.58,2321.44 h60
  text "Component Side - Solder Side" at 10024.74,2321.44 h60
  text "3" at 8421.87,2197.12 h60
  text "214.57mil (5.450mm)" at 8753.87,2197.12 h60
  text "PTH" at 9390.44,2197.12 h60
  text "Round" at 9649.58,2197.12 h60
  text "Component Side - Solder Side" at 10024.74,2197.12 h60
  text "160 Total" at 8421.87,2072.8 h60
  text ".Layer_Name" at 577,-858.49 h60
M17 Embedded Cavity:
  text ".Layer_Name" at 577,-858.49 h60
M18 Embedded Assembly:
  text ".Layer_Name" at 577,-858.49 h60
M19 Embedded Keepout:
  text ".Layer_Name" at 577,-858.49 h60

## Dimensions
0,-400 to 1000,-400 on M2 Board Dimensions
0,0 to 0,3500 on M2 Board Dimensions
0,0 to 5000,0 on M2 Board Dimensions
